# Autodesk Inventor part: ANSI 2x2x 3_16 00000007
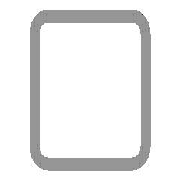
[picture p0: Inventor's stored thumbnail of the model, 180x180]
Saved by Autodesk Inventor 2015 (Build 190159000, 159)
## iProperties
IsCustomPart: 1
Created: 2007-02
Part Number: ANSI 2x2x 3_16 00000007
Material: Steel
Document SubType Name: Modeling
Standard: AISC
Designer: Autodesk, Inc.
Size Designation: 2x2x3/16
Stock Number: 2x2x 3/16
Density: 7.85 g/cm^3
Description: Tube
Standards Organization: ANSI
Language: en-US
Categories: <MemberInstance><Categories><Category DisplayName="Structural Shapes" InternalName="089c4875-fa83-4c05-b084-43b9cc11f5ed" Mnemonic="GRDR"><CategoryParameter Dis
Mass: 6278.25 g
Surface Area: 3375.01 cm^2
Volume: 799.777 cm^3
Appearance: Steel
_FrameMemberDoc: Frame Member File
_Version: 15.0.0
_CCFamilyMember: 1
_CCFamilyDisplayName: ANSI AISC (Square) - Tube
G_L: 38.465 in
G_W: 2.000 in
G_H: 2.000 in
+C35D4425-D849-4D5F-B97B-843782012EA7+CUTDETAIL1: Cut
Author: Autodesk, Inc.
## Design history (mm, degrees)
node "Start plane"
node "End plane"
sketch "Sketch"
  geometry: L1 (-25.4, -15.875)-(-25.4, 15.875); L2 (-15.875, 25.4)-(15.875, 25.4); L3 (25.4, 15.875)-(25.4, -15.875); L4 (15.875, -25.4)-(-15.875, -25.4); L5 (-15.875, 20.637)-(15.875, 20.638); L6 (20.637, 15.875)-(20.637, -15.875); L7 (15.875, -20.637)-(-15.875, -20.638); L8 (-20.637, -15.875)-(-20.637, 15.875); L9 (0, 38.322)-(0, -38.322) reference; L10 (-38.322, 0)-(38.322, 0) reference; A1 r 9.525 centre (-15.875, -15.875) between (-25.4, -15.875) and (-15.875, -25.4); A2 r 9.525 centre (-15.875, 15.875) between (-15.875, 25.4) and (-25.4, 15.875); A3 r 9.525 centre (15.875, 15.875) between (25.4, 15.875) and (15.875, 25.4); A4 r 9.525 centre (15.875, -15.875) between (15.875, -25.4) and (25.4, -15.875); A5 r 4.762 centre (-15.875, 15.875) between (-15.875, 20.637) and (-20.637, 15.875); A6 r 4.762 centre (15.875, 15.875) between (20.637, 15.875) and (15.875, 20.638); A7 r 4.762 centre (15.875, -15.875) between (15.875, -20.637) and (20.637, -15.875); A8 r 4.762 centre (-15.875, -15.875) between (-20.637, -15.875) and (-15.875, -20.638)
  constraints: 16 end point, 16 point on circle, 8 centre point, 8 tangent, 4 parallel, 3 equal radius, 2 perpendicular, 7 other
  dimensions: "d10" = 50.8 distance between parallel lines of L2 L4 (= G_H); "d11" = 50.8 distance between parallel lines of L1 L3 (= G_W); "d12" = 4.7625 distance between parallel lines of L3 L6 (= G_T); "d15" = 25.4 distance between parallel lines of L2 L10 (= 0.5 x d10); "d16" = 25.4 distance between parallel lines of L9 L3 (= 0.5 x d11); "d17" = 9.525 radius of A1 (= G_IR)
extrude "Body" new body sketch "Sketch" stored distance "d3" = 977 (= G_L); taper "d4" = 0 deg
node "Driven Length"
  sketch "Sketch3"
    geometry: L1 (0, 0)-(10, 0) reference
    constraints: 2 end point, 1 horizontal
  workplane "Work Plane4"
  sketch "Sketch4"
    geometry: L1 (-2, -76.2)-(12, -76.2) reference; L2 (-2, 900.8)-(12, 900.8) reference
    dimensions: "d19" = 977 distance between parallel lines of L1 L2 (derived)
workplane "Work Plane3"
split "Split1"
body "Solid1"
other parameters: "G_W" = 50.8 [user parameter; used in 1 equation term], "G_H" = 50.8 [user parameter; used in 1 equation term], "G_T" = 4.7625 [user parameter; used in 1 equation term], "G_IR" = 9.525 [user parameter; used in 1 equation term], "G_L" = 977 (= d19) [user parameter; used in 1 equation term], "G_OFFSET_START" = 76.2 [user parameter; used in 1 equation term], "G_OFFSET_END" = 0 [user parameter; used in 1 equation term], "d13" = -76.2 (= -G_OFFSET_START), "d14" = 900.8 (= G_OFFSET_END + B_L), "B_L" = 900.8 [user parameter; used in 1 equation term], "d18" = 90 deg
